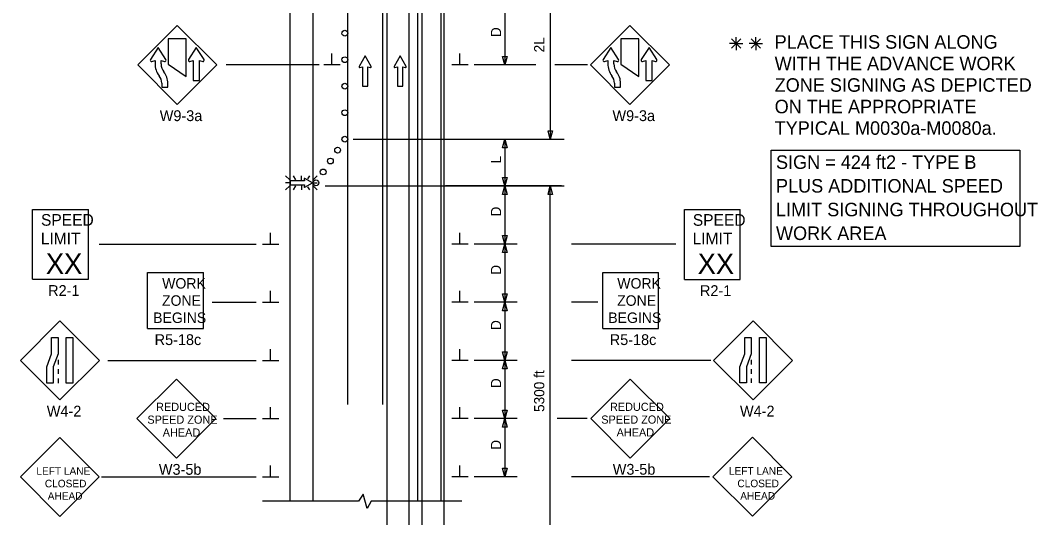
# Model space of a CAD drawing. Extents: x 16729 to 18482, y 7002 to 8333.
# Drawn here: x 16729 to 17429, y 7543 to 7884 of the extents above; entities that cross this region are included whole.
import ezdxf

# ---------------------------------------------------------------- set-up
doc = ezdxf.new("R2010")
doc.units = 0
for name, color, linetype in [('ALI_LEGAL_EX', 7, 'Continuous'), ('MT_SCRATCH_LEVEL_E', 7, 'Continuous'), ('PAVT_EDGE_EX', 7, 'Continuous'), ('TRAFFIC_SIGNS_PR', 7, 'Continuous'), ('TYPICAL_TEXT_DIMEN_EX', 7, 'Continuous'), ('TYPICAL_TEXT_DIMEN_PR', 7, 'Continuous')]:
    doc.layers.add(name, color=color, linetype=linetype)

msp = doc.modelspace()

# ---------------------------------------------------------------- linework, layer by layer
at = {"layer": 'ALI_LEGAL_EX'}
for p, q in [((16980.68, 8333.08), (16980.68, 7514.94)), ((17004.68, 8333.08), (17004.68, 7514.94)), ((16995.95, 8289.26), (16995.95, 7471.12)), ((17019.95, 8289.26), (17019.95, 7471.12)), ((16953.87, 7620.35), (16953.87, 8241.48)), ((16977.87, 7620.35), (16977.87, 8241.48))]:
    msp.add_line(p, q, dxfattribs=at)
for points in [[(16953.87, 7827.42), (16953.87, 7852.42)], [(16977.87, 7827.42), (16977.87, 7852.42)], [(16953.87, 7727.42), (16953.87, 7752.42)], [(16977.87, 7727.42), (16977.87, 7752.42)], [(16953.87, 7627.42), (16953.87, 7652.42)], [(16977.87, 7627.42), (16977.87, 7652.42)]]:
    msp.add_lwpolyline(points, dxfattribs=at)
at = {"layer": 'MT_SCRATCH_LEVEL_E'}
for p, q in [((16965.77, 7859.93), (16961.66, 7852.69)), ((16969.92, 7852.69), (16965.77, 7859.93)), ((16989.82, 7859.93), (16985.71, 7852.69)), ((16993.97, 7852.69), (16989.82, 7859.93)), ((16962.14, 7852.01), (16963.92, 7852.32)), ((16963.92, 7852.32), (16963.92, 7839.07)), ((16967.66, 7839.07), (16967.66, 7852.32)), ((16967.66, 7852.32), (16969.44, 7852.01)), ((16986.19, 7852.01), (16987.97, 7852.32)), ((16987.97, 7852.32), (16987.97, 7839.07)), ((16991.71, 7839.07), (16991.71, 7852.32)), ((16991.71, 7852.32), (16993.49, 7852.01)), ((16963.92, 7839.07), (16967.66, 7839.07)), ((16987.97, 7839.07), (16991.71, 7839.07))]:
    msp.add_line(p, q, dxfattribs=at)
for centre, start, end in [((16962.07, 7852.47), 150.42484, 279.96381), ((16969.51, 7852.47), 260.03619, 29.77312), ((16986.12, 7852.47), 150.42484, 279.96381), ((16993.56, 7852.47), 260.03619, 29.77312)]:
    msp.add_arc(centre, 0.463, start, end, dxfattribs=at)
at = {"layer": 'PAVT_EDGE_EX'}
for p, q in [((16913.87, 8212.75), (16913.87, 7553.94)), ((16929.87, 8212.75), (16929.87, 7553.94)), ((17001.87, 8212.75), (17001.87, 7553.94)), ((17017.87, 8212.75), (17017.87, 7553.94))]:
    msp.add_line(p, q, dxfattribs=at)
at = {"layer": 'TRAFFIC_SIGNS_PR'}
for p, q in [((16836.51, 7880.87), (16809.35, 7853.71)), ((16863.66, 7853.71), (16836.51, 7880.87)), ((17148.01, 7880.86), (17120.86, 7853.71)), ((17175.16, 7853.71), (17148.01, 7880.86)), ((16809.35, 7853.71), (16836.51, 7826.56)), ((16836.51, 7826.56), (16863.66, 7853.71)), ((17120.86, 7853.71), (17148.01, 7826.56)), ((17148.01, 7826.56), (17175.16, 7853.71)), ((16913.89, 7774.65), (16911.06, 7777.47)), ((16916.18, 7777.47), (16917.81, 7774.65)), ((16921.97, 7774.65), (16921.97, 7777.47)), ((16927.44, 7777.47), (16926.23, 7775.37)), ((16932.87, 7777.46), (16930.06, 7774.65)), ((16913.89, 7772.61), (16911.06, 7772.61)), ((16913.89, 7770.58), (16911.06, 7767.76)), ((16917.83, 7770.58), (16916.21, 7767.76)), ((16921.97, 7770.58), (16921.97, 7767.76)), ((16926.15, 7769.95), (16927.41, 7767.76)), ((16930.06, 7772.61), (16932.87, 7772.61)), ((16932.87, 7767.76), (16930.06, 7770.58)), ((16737, 7754.34), (16775.4, 7754.34)), ((16737, 7706.34), (16737, 7754.34)), ((16775.4, 7706.34), (16775.4, 7754.34)), ((17185.47, 7754.29), (17223.87, 7754.29)), ((17185.47, 7706.29), (17185.47, 7754.29)), ((17223.87, 7706.29), (17223.87, 7754.29)), ((16816.13, 7672.58), (16816.13, 7710.98)), ((16816.13, 7710.98), (16854.53, 7710.98)), ((16854.53, 7672.58), (16854.53, 7710.98)), ((17129.27, 7672.58), (17129.27, 7710.98)), ((17129.27, 7710.98), (17167.67, 7710.98)), ((17167.67, 7672.58), (17167.67, 7710.98)), ((16737, 7706.34), (16775.4, 7706.34)), ((17185.47, 7706.29), (17223.87, 7706.29)), ((16755.78, 7677.72), (16728.63, 7650.57)), ((16782.93, 7650.57), (16755.78, 7677.72)), ((16816.13, 7672.58), (16854.53, 7672.58)), ((17129.27, 7672.58), (17167.67, 7672.58)), ((17232.73, 7677.73), (17205.57, 7650.58)), ((17259.88, 7650.58), (17232.73, 7677.73)), ((16754.53, 7651.06), (16754.53, 7647.86)), ((17231.48, 7651.07), (17231.48, 7647.87)), ((16728.63, 7650.57), (16755.78, 7623.42)), ((16754.53, 7644.66), (16754.53, 7641.46)), ((16755.78, 7623.42), (16782.93, 7650.57)), ((17205.57, 7650.58), (17232.73, 7623.43)), ((17231.48, 7644.67), (17231.48, 7641.47)), ((17232.73, 7623.43), (17259.88, 7650.58)), ((16754.53, 7638.26), (16754.53, 7635.06)), ((16835.9, 7637.71), (16808.75, 7610.55)), ((16863.05, 7610.55), (16835.9, 7637.71)), ((17148.2, 7637.76), (17121.04, 7610.61)), ((17175.35, 7610.61), (17148.2, 7637.76)), ((17231.48, 7638.27), (17231.48, 7635.07)), ((16808.75, 7610.55), (16835.9, 7583.4)), ((16835.9, 7583.4), (16863.05, 7610.55)), ((17121.04, 7610.61), (17148.2, 7583.45)), ((17148.2, 7583.45), (17175.35, 7610.61)), ((16755.7, 7597.71), (16728.54, 7570.56)), ((16782.85, 7570.56), (16755.7, 7597.71)), ((17232.21, 7597.79), (17205.06, 7570.64)), ((17259.36, 7570.64), (17232.21, 7597.79)), ((16728.54, 7570.56), (16755.7, 7543.4)), ((16755.7, 7543.4), (16782.85, 7570.56)), ((17205.06, 7570.64), (17232.21, 7543.49)), ((17232.21, 7543.49), (17259.36, 7570.64))]:
    msp.add_line(p, q, dxfattribs=at)
for points in [[(16830.2, 7871.64), (16830.2, 7854.3), (16842.6, 7845.68), (16842.6, 7871.64)], [(17141.7, 7871.64), (17141.7, 7854.3), (17154.11, 7845.68), (17154.11, 7871.64)], [(16754.53, 7666.31), (16754.53, 7655.12), (16751.19, 7646.24), (16751.19, 7635.06), (16746.7, 7635.06), (16746.7, 7646.24), (16750.04, 7655.12), (16750.04, 7666.31)], [(16764.67, 7666.31), (16764.67, 7635.06), (16760.18, 7635.06), (16760.18, 7666.31)], [(17231.48, 7666.32), (17231.48, 7655.14), (17228.13, 7646.25), (17228.13, 7635.07), (17223.64, 7635.07), (17223.64, 7646.25), (17226.98, 7655.14), (17226.98, 7666.32)], [(17241.61, 7666.32), (17241.61, 7635.07), (17237.12, 7635.07), (17237.12, 7666.32)]]:
    msp.add_lwpolyline(points, close=True, dxfattribs=at)
for points in [[(16828.7, 7857.42), (16823.37, 7865.79), (16818.04, 7857.42)], [(16854.92, 7857.42), (16849.6, 7865.79), (16844.27, 7857.42)], [(17140.21, 7857.41), (17134.88, 7865.78), (17129.55, 7857.41)], [(17166.43, 7857.41), (17161.11, 7865.78), (17155.78, 7857.41)], [(16818.98, 7856.15), (16821.27, 7856.79), (16821.27, 7854.55)], [(16825.46, 7854.45), (16825.47, 7856.79), (16827.77, 7856.16)], [(16845.21, 7856.15), (16847.5, 7856.79), (16847.5, 7842.99), (16851.7, 7842.99), (16851.7, 7856.79), (16854, 7856.16)], [(17130.48, 7856.15), (17132.78, 7856.78), (17132.77, 7854.55)], [(17136.97, 7854.45), (17136.97, 7856.78), (17139.27, 7856.15)], [(17156.71, 7856.15), (17159.01, 7856.78), (17159.01, 7842.98), (17163.2, 7842.98), (17163.2, 7856.78), (17165.5, 7856.15)], [(16825.84, 7841.1), (16825.83, 7838.45), (16830.03, 7838.45), (16830.03, 7841.1)], [(17137.34, 7841.1), (17137.34, 7838.45), (17141.54, 7838.45), (17141.54, 7841.1)], [(16923.8, 7775.3), (16924.03, 7774), (16914.3, 7774), (16914.3, 7771.26), (16924.03, 7771.26), (16923.8, 7769.95)], [(16924.3, 7769.6), (16929.61, 7772.61), (16924.3, 7775.65)]]:
    msp.add_lwpolyline(points, dxfattribs=at)
for centre in [(16951.8, 7875.54), (16951.8, 7857.32), (16951.8, 7839.12), (16951.8, 7820.89), (16951.8, 7802.68), (16946.83, 7795.17), (16941.87, 7787.66), (16936.9, 7780.16), (16931.93, 7772.66)]:
    msp.add_circle(centre, 2, dxfattribs=at)
for centre, radius, start, end in [((16818.75, 7856.96), 0.84, 147.52044, 285.3986), ((16833.86, 7854.19), 12.59, 178.32933, 218.54273), ((16814.97, 7854.78), 10.5, 358.18937, 0.00483), ((16833.86, 7854.19), 8.4, 178.19356, 218.54646), ((16827.99, 7856.97), 0.842, 254.68281, 32.2708), ((16824.99, 7846.03), 10.5, 74.67996, 74.68078), ((16837.55, 7863.05), 10.5, 212.45689, 212.46649), ((16844.98, 7856.96), 0.841, 147.54971, 285.33159), ((16854.22, 7856.96), 0.839, 254.67777, 32.46648), ((16863.78, 7863.05), 10.5, 212.45689, 212.46649), ((17130.26, 7856.96), 0.84, 147.52044, 285.3986), ((17145.36, 7854.18), 12.59, 178.32933, 218.54273), ((17145.36, 7854.18), 8.4, 178.19356, 218.54646), ((17126.47, 7854.78), 10.5, 358.18937, 0.00483), ((17139.49, 7856.96), 0.842, 254.68281, 32.2708), ((17136.5, 7846.03), 10.5, 74.67996, 74.68078), ((17149.06, 7863.05), 10.5, 212.45689, 212.46649), ((17156.49, 7856.96), 0.841, 147.54971, 285.33159), ((17165.72, 7856.96), 0.839, 254.67777, 32.46648), ((17175.29, 7863.05), 10.5, 212.45689, 212.46649), ((16817.43, 7841.1), 12.6, 0, 38.5422), ((17128.94, 7841.1), 12.6, 0, 38.5422), ((16817.43, 7841.1), 8.4, 0, 38.54567), ((17128.94, 7841.1), 8.4, 0, 38.54567), ((16924.13, 7775.35), 0.341, 61.48329, 189.95933), ((16924.13, 7769.9), 0.341, 170.73078, 298.89165)]:
    msp.add_arc(centre, radius, start, end, dxfattribs=at)
at = {"layer": 'TYPICAL_TEXT_DIMEN_EX'}
msp.add_lwpolyline([(17245.22, 7795.05), (17416.15, 7795.05), (17416.15, 7728.88), (17245.22, 7728.88)], close=True, dxfattribs=at)
at = {"layer": 'TYPICAL_TEXT_DIMEN_PR'}
for p, q in [((17093.18, 7920.56), (17093.18, 7802.68)), ((17061.87, 7893.75), (17061.87, 7853.75)), ((17221.1, 7868.38), (17216.56, 7868.38)), ((17217.91, 7871.57), (17224.28, 7865.19)), ((17224.28, 7871.57), (17217.91, 7865.19)), ((17221.1, 7868.38), (17221.1, 7872.83)), ((17221.1, 7868.38), (17224.28, 7868.38)), ((17221.1, 7868.38), (17225.57, 7868.38)), ((17221.1, 7868.38), (17221.1, 7863.88)), ((17234.6, 7868.38), (17230.07, 7868.38)), ((17237.79, 7871.57), (17231.41, 7865.19)), ((17231.42, 7871.57), (17237.79, 7865.19)), ((17234.6, 7868.38), (17234.6, 7872.83)), ((17234.6, 7868.38), (17237.79, 7868.38)), ((17234.6, 7868.38), (17239.08, 7868.38)), ((17234.6, 7868.38), (17234.6, 7863.88)), ((16942.91, 7853.75), (16942.91, 7861.53)), ((17030.99, 7853.75), (17030.99, 7861.53)), ((16934.08, 7853.75), (16870.09, 7853.75)), ((16948.53, 7853.75), (16937.28, 7853.75)), ((17036.62, 7853.75), (17025.37, 7853.75)), ((17083.26, 7853.75), (17040.87, 7853.75)), ((17061.87, 7853.75), (17060.3, 7859.61)), ((17060.3, 7859.61), (17061.87, 7859.61)), ((17061.87, 7859.61), (17063.44, 7859.61)), ((17063.44, 7859.61), (17061.87, 7853.75)), ((17118.84, 7853.75), (17096.22, 7853.75)), ((17093.18, 7802.68), (17091.61, 7808.54)), ((17091.61, 7808.54), (17093.18, 7808.54)), ((17093.18, 7808.54), (17094.75, 7808.54)), ((17094.75, 7808.54), (17093.18, 7802.68)), ((16957.62, 7802.68), (17066.87, 7802.68)), ((16957.62, 7802.68), (17102.73, 7802.68)), ((17060.3, 7796.82), (17061.87, 7802.68)), ((17061.87, 7802.68), (17061.87, 7770.57)), ((17061.87, 7802.68), (17063.44, 7796.82)), ((17061.87, 7796.82), (17060.3, 7796.82)), ((17063.44, 7796.82), (17061.87, 7796.82)), ((16938.26, 7770.57), (17102.73, 7770.57)), ((16957.62, 7770.57), (17066.87, 7770.57)), ((17100.98, 7770.57), (17021.17, 7770.57)), ((17061.87, 7770.57), (17060.3, 7776.44)), ((17060.3, 7776.44), (17061.87, 7776.44)), ((17060.3, 7764.71), (17061.87, 7770.57)), ((17061.87, 7776.44), (17063.44, 7776.44)), ((17063.44, 7776.44), (17061.87, 7770.57)), ((17061.87, 7770.57), (17061.87, 7730.57)), ((17061.87, 7770.57), (17063.44, 7764.71)), ((17091.62, 7764.71), (17093.19, 7770.57)), ((17093.18, 7500.77), (17093.18, 7770.57)), ((17093.19, 7770.57), (17094.76, 7764.71)), ((17061.87, 7764.71), (17060.3, 7764.71)), ((17063.44, 7764.71), (17061.87, 7764.71)), ((17093.19, 7764.71), (17091.62, 7764.71)), ((17094.76, 7764.71), (17093.19, 7764.71)), ((16900.74, 7730.57), (16900.74, 7738.36)), ((16900.74, 7730.57), (16900.74, 7738.36)), ((17030.99, 7730.57), (17030.99, 7738.36)), ((17061.87, 7730.57), (17060.3, 7736.44)), ((17060.3, 7736.44), (17061.87, 7736.44)), ((17061.87, 7736.44), (17063.44, 7736.44)), ((17063.44, 7736.44), (17061.87, 7730.57)), ((16782.69, 7730.57), (16890.87, 7730.57)), ((16866.23, 7730.57), (16890.87, 7730.57)), ((16895.12, 7730.57), (16906.37, 7730.57)), ((16895.12, 7730.57), (16906.37, 7730.57)), ((17036.62, 7730.57), (17025.37, 7730.57)), ((17070.41, 7730.57), (17040.87, 7730.57)), ((17060.3, 7724.71), (17061.87, 7730.57)), ((17061.87, 7730.57), (17061.87, 7690.57)), ((17061.87, 7730.57), (17063.44, 7724.71)), ((17179.55, 7730.57), (17107.79, 7730.57)), ((17061.87, 7724.71), (17060.3, 7724.71)), ((17063.44, 7724.71), (17061.87, 7724.71)), ((16900.74, 7690.57), (16900.74, 7698.36)), ((16900.74, 7690.57), (16900.74, 7698.36)), ((17030.99, 7690.57), (17030.99, 7698.36)), ((17061.87, 7690.57), (17060.3, 7696.44)), ((17060.3, 7696.44), (17061.87, 7696.44)), ((17061.87, 7696.44), (17063.44, 7696.44)), ((17063.44, 7696.44), (17061.87, 7690.57)), ((16860.61, 7690.57), (16890.87, 7690.57)), ((16864.87, 7690.57), (16890.87, 7690.57)), ((16895.12, 7690.57), (16906.37, 7690.57)), ((16895.12, 7690.57), (16906.37, 7690.57)), ((17036.62, 7690.57), (17025.37, 7690.57)), ((17070.41, 7690.57), (17040.87, 7690.57)), ((17060.3, 7684.71), (17061.87, 7690.57)), ((17061.87, 7690.57), (17061.87, 7650.57)), ((17061.87, 7690.57), (17063.44, 7684.71)), ((17125.95, 7690.57), (17107.79, 7690.57)), ((17061.87, 7684.71), (17060.3, 7684.71)), ((17063.44, 7684.71), (17061.87, 7684.71)), ((16900.74, 7650.57), (16900.74, 7658.36)), ((16900.74, 7650.57), (16900.74, 7658.36)), ((17030.99, 7650.57), (17030.99, 7658.36)), ((17061.87, 7650.57), (17060.3, 7656.44)), ((17060.3, 7656.44), (17061.87, 7656.44)), ((17061.87, 7656.44), (17063.44, 7656.44)), ((17063.44, 7656.44), (17061.87, 7650.57)), ((16788.78, 7650.57), (16890.87, 7650.57)), ((16878.29, 7650.57), (16890.87, 7650.57)), ((16895.12, 7650.57), (16906.37, 7650.57)), ((16895.12, 7650.57), (16906.37, 7650.57)), ((17036.62, 7650.57), (17025.37, 7650.57)), ((17070.41, 7650.57), (17040.87, 7650.57)), ((17060.3, 7644.71), (17061.87, 7650.57)), ((17061.87, 7644.71), (17060.3, 7644.71)), ((17061.87, 7650.57), (17063.44, 7644.71)), ((17061.87, 7650.57), (17061.87, 7610.57)), ((17063.44, 7644.71), (17061.87, 7644.71)), ((17203.58, 7650.57), (17107.79, 7650.57)), ((16900.74, 7610.57), (16900.74, 7618.36)), ((16900.74, 7610.57), (16900.74, 7618.36)), ((17030.99, 7610.57), (17030.99, 7618.36)), ((17061.87, 7610.57), (17060.3, 7616.44)), ((17060.3, 7616.44), (17061.87, 7616.44)), ((17061.87, 7616.44), (17063.44, 7616.44)), ((17063.44, 7616.44), (17061.87, 7610.57)), ((16868.24, 7610.57), (16890.87, 7610.57)), ((16895.12, 7610.57), (16906.37, 7610.57)), ((16895.12, 7610.57), (16906.37, 7610.57)), ((17036.62, 7610.57), (17025.37, 7610.57)), ((17070.41, 7610.57), (17040.87, 7610.57)), ((17060.3, 7604.71), (17061.87, 7610.57)), ((17061.87, 7610.57), (17061.87, 7570.57)), ((17061.87, 7610.57), (17063.44, 7604.71)), ((17118.62, 7610.57), (17097.83, 7610.57)), ((17061.87, 7604.71), (17060.3, 7604.71)), ((17063.44, 7604.71), (17061.87, 7604.71)), ((16900.74, 7570.57), (16900.74, 7578.36)), ((17030.99, 7570.57), (17030.99, 7578.36)), ((17061.87, 7570.57), (17060.3, 7576.44)), ((17060.3, 7576.44), (17061.87, 7576.44)), ((17061.87, 7576.44), (17063.44, 7576.44)), ((17063.44, 7576.44), (17061.87, 7570.57)), ((16784.42, 7570.57), (16890.87, 7570.57)), ((16895.12, 7570.57), (16906.37, 7570.57)), ((17036.62, 7570.57), (17025.37, 7570.57)), ((17070.41, 7570.57), (17040.87, 7570.57)), ((17202.62, 7570.57), (17107.79, 7570.57)), ((16961.21, 7553.94), (16895.27, 7553.94)), ((16964.47, 7558.74), (16961.21, 7553.94)), ((16967.21, 7548.8), (16964.47, 7558.74)), ((16969.95, 7553.94), (16967.21, 7548.8)), ((17032.29, 7553.94), (16969.95, 7553.94))]:
    msp.add_line(p, q, dxfattribs=at)

# ---------------------------------------------------------------- texts
at = {"layer": 'TRAFFIC_SIGNS_PR'}
for s, height, p in [('W9-3a', 7.44, (16824.44, 7815.12)), ('W9-3a', 7.44, (17135.95, 7815.12)), ('SPEED', 8, (16742.77, 7743.2)), ('SPEED', 8, (17191.24, 7743.15)), ('LIMIT', 8, (16742.61, 7730.4)), ('LIMIT', 8, (17191.08, 7730.35)), ('XX', 14.031, (16746.11, 7710.1)), ('XX', 14.031, (17194.59, 7710.05)), ('WORK', 7.217, (16826.13, 7699.95)), ('WORK', 7.217, (17139.27, 7699.95)), ('R2-1', 7.44, (16747.68, 7694.9)), ('R2-1', 7.44, (17196.15, 7694.85)), ('ZONE', 7.217, (16826.01, 7688.14)), ('ZONE', 7.217, (17139.15, 7688.14)), ('BEGINS', 7.217, (16819.94, 7676.33)), ('BEGINS', 7.217, (17133.08, 7676.33)), ('R5-18c', 7.44, (16820.94, 7661.14)), ('R5-18c', 7.44, (17134.08, 7661.14)), ('W4-2', 7.44, (16746.74, 7611.98)), ('REDUCED', 5.6, (16821.96, 7615.86)), ('REDUCED', 5.6, (17134.25, 7615.91)), ('W4-2', 7.44, (17223.68, 7611.99)), ('SPEED ZONE', 5.6, (16815.95, 7607.06)), ('SPEED ZONE', 5.6, (17128.24, 7607.11)), ('AHEAD', 5.6, (16826.51, 7598.26)), ('AHEAD', 5.6, (17138.81, 7598.31)), ('LEFT LANE', 5.2, (16739.58, 7571.95)), ('W3-5b', 7.44, (16823.85, 7571.96)), ('W3-5b', 7.44, (17136.15, 7572.01)), ('LEFT LANE', 5.2, (17216.09, 7572.03)), ('CLOSED', 5.2, (16745.41, 7563.35)), ('CLOSED', 5.2, (17221.92, 7563.43)), ('AHEAD', 5.2, (16747.36, 7554.75)), ('AHEAD', 5.2, (17223.87, 7554.83))]:
    msp.add_text(s, height=height, dxfattribs=at).set_placement(p)
at = {"layer": 'TYPICAL_TEXT_DIMEN_EX'}
for s, p in [('PLACE THIS SIGN ALONG', (17247.55, 7864.88)), ('WITH THE ADVANCE WORK', (17247.55, 7850.08)), ('ZONE SIGNING AS DEPICTED', (17247.55, 7835.28)), ('ON THE APPROPRIATE', (17247.55, 7820.48)), ('TYPICAL M0030a-M0080a.', (17247.55, 7805.68)), ('SIGN = 424 ft2 - TYPE B', (17248.47, 7782.27)), ('PLUS ADDITIONAL SPEED', (17248.47, 7765.97)), ('LIMIT SIGNING THROUGHOUT', (17248.47, 7749.67)), ('WORK AREA', (17248.47, 7733.37))]:
    msp.add_text(s, height=9.3, dxfattribs=at).set_placement(p)
at = {"layer": 'TYPICAL_TEXT_DIMEN_PR'}
for s, p in [('D', (17059.31, 7872.86)), ('2L', (17089.05, 7862.34)), ('L', (17059.31, 7785.98)), ('D', (17059.31, 7749.54)), ('D', (17059.31, 7709.48)), ('D', (17059.31, 7671.5)), ('5300 ft', (17089.06, 7615.14)), ('D', (17059.31, 7631.54)), ('D', (17059.31, 7589.17))]:
    msp.add_text(s, height=7, rotation=90, dxfattribs=at).set_placement(p)

doc.saveas('drawing.dxf')
